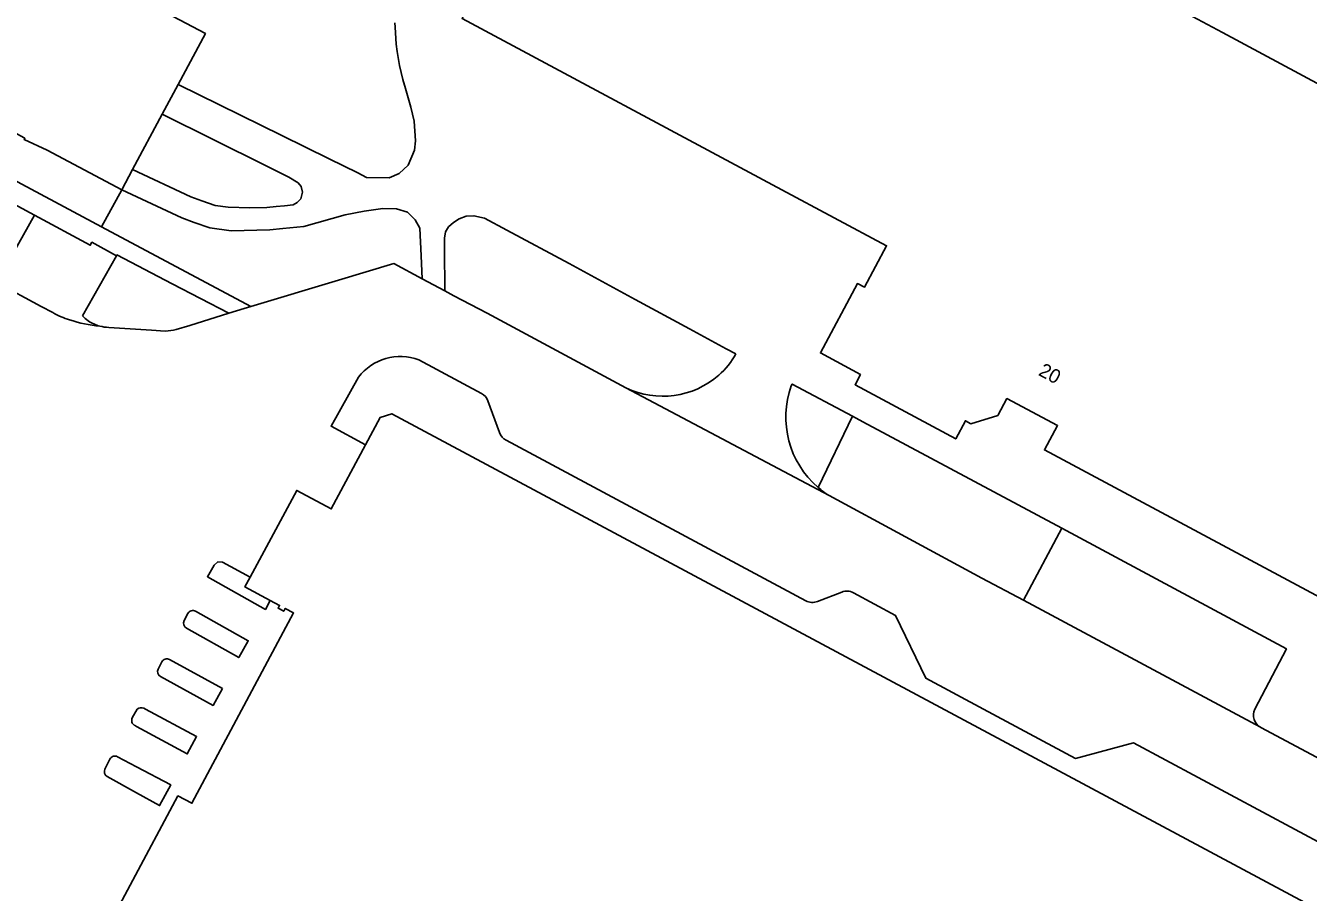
# Model space of a CAD drawing. Extents: x 159489 to 160304, y 383826 to 384530.
# Drawn here: x 159992.1 to 160083.4, y 383987 to 384048.7 of the extents above; entities that cross this region are included whole.
import ezdxf

# ---------------------------------------------------------------- set-up
doc = ezdxf.new("R2010")
doc.units = 0
for name, color, linetype in [('IMGEO_Pand', 7, 'Continuous'), ('IMGEO_Pand_nummerreeks', 7, 'Continuous'), ('IMGEO_Parkeervlak_open', 7, 'Continuous'), ('IMGEO_Rijbaan_lokaal_open', 7, 'Continuous'), ('IMGEO_Voetpad_open', 7, 'Continuous')]:
    doc.layers.add(name, color=color, linetype=linetype)

msp = doc.modelspace()

# ---------------------------------------------------------------- linework, layer by layer
at = {"layer": 'IMGEO_Pand'}
for points in [[(160073.755, 384058.611), (160074.776, 384058.065), (160074.653, 384057.835), (160074.445, 384057.447), (160075.061, 384057.116), (160072.374, 384052.088), (160071.43, 384052.592), (160070.91, 384051.621), (160077.333, 384048.184), (160084.358, 384044.424), (160120.106, 384025.292)], [(159999.813, 384050.821), (160004.907, 384048.107), (160002.967, 384044.489)], [(160104.986, 383996.869), (160064.654, 384018.46), (160065.584, 384020.199), (160061.979, 384022.125), (160061.323, 384020.913), (160059.421, 384020.326), (160059.025, 384020.543), (160058.336, 384019.253), (160051.165, 384023.109), (160051.552, 384023.83), (160048.693, 384025.369), (160051.335, 384030.308), (160051.828, 384030.043), (160053.413, 384033.006), (160045.958, 384036.994), (160023.177, 384049.18), (160023.352, 384049.507), (160022.646, 384049.884), (160022.471, 384049.558), (160021.766, 384049.936)], [(159977.223, 384048.598), (159987.204, 384043.143), (159988.813, 384042.4), (159992.053, 384040.657), (159992.006, 384040.568), (159993.634, 384039.812), (159998.944, 384036.986)], [(160002.967, 384044.489), (160001.836, 384042.38)], [(159999.719, 384038.431), (160001.836, 384042.38)], [(159999.719, 384038.431), (159998.944, 384036.986)], [(160090.592, 383982.276), (160018.179, 384021.039), (160017.35, 384020.78), (160016.309, 384018.831)], [(160008.094, 384009.408), (160011.404, 384015.579), (160013.867, 384014.258), (160016.309, 384018.831)], [(160008.094, 384009.408), (160007.719, 384008.708), (160009.521, 384007.745)], [(159989.335, 383968.396), (160002.95, 383993.83), (160003.94, 383993.299), (160011.184, 384006.857), (160010.585, 384007.176), (160010.482, 384006.982), (160010.086, 384007.194), (160010.19, 384007.387), (160009.521, 384007.745)]]:
    msp.add_lwpolyline(points, dxfattribs=at)
at = {"layer": 'IMGEO_Parkeervlak_open'}
msp.add_lwpolyline([(159996.149, 384028.009), (159998.57, 384032.286)], dxfattribs=at)
for centre, radius, start, end in [((160000.825, 384032.943), 6.798, 226.54144, 231.04636), ((159998.105, 384029.973), 2.788, 236.13953, 255.08621)]:
    msp.add_arc(centre, radius, start, end, dxfattribs=at)
at = {"layer": 'IMGEO_Rijbaan_lokaal_open'}
for points in [[(160020.34, 384030.653), (160018.329, 384031.734), (160014.376, 384030.545), (160008.131, 384028.667)], [(159994.052, 384028.245), (159993.218, 384028.677), (159990.033, 384030.375)], [(160021.949, 384029.788), (160020.34, 384030.653)], [(160034.853, 384022.885), (160024.957, 384028.212), (160022.599, 384029.439), (160021.949, 384029.788)], [(160006.585, 384028.193), (160003.802, 384027.333), (160002.83, 384027.039)], [(160008.131, 384028.667), (160007.666, 384028.527), (160006.585, 384028.193)], [(160002.049, 384026.93), (160001.056, 384026.985), (159998.03, 384027.186)], [(160020.108, 384024.875), (160024.558, 384022.49)], [(160016.309, 384018.831), (160013.85, 384020.15), (160015.81, 384023.643)], [(160049.329, 384015.207), (160034.853, 384022.885)], [(160025.025, 384021.95), (160025.843, 384019.697)], [(160026.312, 384019.156), (160047.657, 384007.723)], [(160063.157, 384007.772), (160060.193, 384009.342), (160049.329, 384015.207)], [(160009.521, 384007.745), (160009.181, 384007.107), (160005.051, 384009.428), (160005.521, 384010.266), (160005.79, 384010.49), (160006.119, 384010.467), (160008.094, 384009.408)], [(160048.49, 384007.672), (160050.22, 384008.341)], [(160051.053, 384008.29), (160054.054, 384006.681), (160056.202, 384002.206), (160060.321, 384000), (160066.869, 383996.493), (160071.001, 383997.599), (160091.719, 383986.495)], [(160004.209, 384006.981), (160007.953, 384004.877), (160007.283, 384003.68), (160003.552, 384005.771)], [(160080.037, 383998.719), (160063.157, 384007.772)], [(160003.392, 384006.306), (160003.66, 384006.817)], [(160001.541, 384002.857), (160001.804, 384003.368)], [(160002.348, 384003.539), (160006.118, 384001.483)], [(160006.118, 384001.483), (160005.446, 384000.273), (160001.705, 384002.322)], [(159999.701, 383999.394), (160000.057, 384000)], [(160000.516, 384000.07), (160000.646, 384000), (160004.278, 383998.047), (160003.615, 383996.815), (160000, 383998.78), (159999.866, 383998.853)], [(160112.894, 383981.13), (160102.73, 383986.602), (160101.565, 383987.222), (160080.061, 383998.706), (160080.037, 383998.719)], [(159997.751, 383995.733), (159998.108, 383996.444)], [(159998.652, 383996.619), (160000, 383995.905), (160002.439, 383994.614), (160001.648, 383993.133), (160000, 383994.047), (159997.915, 383995.203)]]:
    msp.add_lwpolyline(points, dxfattribs=at)
for centre, radius, start, end in [((159996.574, 384032.462), 4.914, 239.11611, 254.19501), ((159998.159, 384036.219), 8.974, 250.99393, 265.0677), ((159998.097, 384029.947), 2.762, 255.10404, 268.61081), ((160001.886, 384030.953), 4.026, 272.32478, 283.56551), ((160018.784, 384021.382), 3.735, 69.23253, 142.75683), ((160024.081, 384021.606), 1.004, 20.03708, 61.67039), ((160026.779, 384020.034), 0.995, 199.82922, 242.01567), ((160050.581, 384007.413), 0.996, 61.71738, 111.27556), ((160004.014, 384006.632), 0.4, 60.83044, 152.43396), ((160048.129, 384008.6), 0.996, 241.71738, 291.27556), ((160003.746, 384006.12), 0.4, 152.3205, 240.97971), ((160002.16, 384003.188), 0.399, 61.79119, 153.10866), ((160001.897, 384002.673), 0.4, 152.69406, 241.39095), ((160000.335, 383999.716), 0.397, 62.91381, 134.4284), ((160000.052, 383999.205), 0.399, 151.7777, 242.14474), ((159998.465, 383996.266), 0.399, 62.15727, 153.50778), ((159998.108, 383995.553), 0.4, 153.23022, 241.15747)]:
    msp.add_arc(centre, radius, start, end, dxfattribs=at)
at = {"layer": 'IMGEO_Voetpad_open'}
for points in [[(159977.223, 384048.598), (159975.813, 384045.96), (159997.515, 384034.347)], [(160018.387, 384048.867), (160018.406, 384048.561), (160018.484, 384047.359), (160018.55, 384046.837), (160018.73, 384045.834), (160018.966, 384044.839), (160019.142, 384044.201), (160019.535, 384042.864), (160019.769, 384041.869), (160019.872, 384040.482), (160019.789, 384039.818), (160019.333, 384038.74), (160018.691, 384038.153), (160017.999, 384037.839), (160016.381, 384037.864), (160015.763, 384038.197), (160013.728, 384039.188), (160010.337, 384040.859), (160002.967, 384044.489)], [(160001.836, 384042.38), (160009.192, 384038.707), (160010.847, 384037.881), (160011.505, 384037.488), (160011.727, 384037.212), (160011.829, 384036.81), (160011.703, 384036.344), (160011.45, 384036.076), (160011.158, 384035.91), (160010.534, 384035.847), (160009.949, 384035.795), (160009.279, 384035.736), (160008.063, 384035.713), (160006.536, 384035.757), (160005.612, 384035.871), (160004.653, 384036.197), (160003.875, 384036.497), (159999.719, 384038.431)], [(159992.733, 384035.186), (159991.544, 384035.829), (159988.473, 384037.455)], [(159998.944, 384036.986), (159997.515, 384034.347)], [(159998.944, 384036.986), (160003.234, 384034.989), (160004.095, 384034.657), (160005.215, 384034.276), (160006.747, 384034.068), (160009.487, 384034.13), (160010.418, 384034.228), (160011.908, 384034.384), (160014.848, 384035.207), (160016.218, 384035.476), (160017.542, 384035.653), (160018.524, 384035.623), (160019.301, 384035.385), (160019.832, 384034.846), (160020.176, 384034.263), (160020.266, 384032.273), (160020.34, 384030.653)], [(159990.033, 384030.375), (159992.733, 384035.186)], [(159998.57, 384032.286), (159996.829, 384033.25), (159996.707, 384033.035), (159992.733, 384035.186)], [(160021.949, 384029.788), (160021.934, 384032.773), (160021.93, 384033.547), (160022.01, 384033.998), (160022.219, 384034.339), (160022.58, 384034.66), (160022.97, 384034.909), (160023.482, 384035.118), (160024.028, 384035.133), (160024.775, 384034.955), (160026.375, 384034.103), (160030.807, 384031.744), (160031.068, 384031.602), (160035.25, 384029.326), (160035.511, 384029.184), (160039.372, 384027.084), (160039.631, 384026.942), (160041.986, 384025.661), (160042.674, 384025.301)], [(159997.515, 384034.347), (160008.131, 384028.667)], [(160006.585, 384028.193), (160002.543, 384030.301), (159998.608, 384032.353), (159998.57, 384032.286)], [(160050.98, 384020.861), (160046.691, 384023.153), (160046.627, 384023.031)], [(160050.98, 384020.861), (160048.527, 384015.798)], [(160065.897, 384012.891), (160051.713, 384020.47), (160050.98, 384020.861)], [(160065.897, 384012.891), (160063.157, 384007.772)], [(160079.622, 384000), (160081.885, 384004.291), (160065.897, 384012.891)]]:
    msp.add_lwpolyline(points, dxfattribs=at)
for centre, radius, start, end in [((160038.25, 384027.618), 4.994, 309.93709, 332.35617), ((160037.473, 384028.317), 6.03, 244.25125, 311.34026), ((160052.823, 384020.793), 6.588, 160.13808, 229.29835), ((160052.795, 384020.75), 6.538, 229.24358, 237.98284), ((160080.515, 383999.582), 0.986, 154.89032, 241.01077)]:
    msp.add_arc(centre, radius, start, end, dxfattribs=at)

# ---------------------------------------------------------------- texts
at = {"layer": 'IMGEO_Pand_nummerreeks'}
msp.add_text('20', height=1, rotation=331.88496, dxfattribs=at).set_placement((160064.156, 384023.819))

doc.saveas('drawing.dxf')
